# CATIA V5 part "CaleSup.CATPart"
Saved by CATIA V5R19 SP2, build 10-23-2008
Part number: CaleSup
Bounding box of the stored display mesh (mm): x 0 to 16, y 0 to 96, z 0 to 53.5
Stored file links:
  D:\SCHOOL\FRANCE\BANC_POUTRE_EN_MOUSSE\CaleSup.CATPart
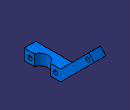
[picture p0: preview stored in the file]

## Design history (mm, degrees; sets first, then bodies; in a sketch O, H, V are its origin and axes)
AxisSystem1: origin (0, 0, 0), X (1, 0, 0), Y (0, 1, 0), Z (0, 0, 1)
Body1 (main body)
  Sketch1 on YZ plane of AxisSystem1, origin (0, 0, 0), H (0, 1, 0), V (0, 0, 1)
    point P1 (0, 15)
    line L1 (0, 15) -> (0, 0)
    line L2 (0, 0) -> (50, 0)
    point P2 (50, 0)
    line L3 (50, 0) -> (96, 46)
    point P3 (96, 46)
    line L4 (96, 46) -> (88.5, 53.5)
    line L5 (88.5, 53.5) -> (50, 15)
    line L6 (50, 15) -> (0, 15)
    construction line L7 (-32.6409, 0) -> (133.7668, 0)
    point P6 (-32.6409, 0)
    axis line L8 (0, 62.3177) -> (0, -36.8999)
    point P8 (0, 62.3177)
    angle L7 L3 = 45
    length L6 = 50
    distance P2 L8 = 50
    distance P3 L7 = 46
    distance L6 L2 = 15
    coincidence: P1 V, P6 H, L7 H, P8 V
    vertical: L1 V, L8 V
    horizontal: L2 H, L6 H
    perpendicularity: L4 L3
    parallelism: L3 L5
  Pad1: profile Sketch1, direction (1, 0, 0), length 20
  Sketch2 on end face of Pad1, origin (20, 85.234, 39.5673), H (0, 1, 0), V (0, 0, 1)
    point P1 (2.266, 5.4327)
    axis line L1 (-24.0475, -20.8808) -> (18.1423, 21.309)
    reference projected line E1 (-2.734, 7.9327) -> (-35.663, -24.9963) from edge [face of Pad1 from Sketch1.L5 | end face of Pad1]
    reference projected line E2 (-35.234, -39.5673) -> (4.766, 0.4327) from edge [face of Pad1 from Sketch1.L3 | end face of Pad1]
    reference projected line E3 (-85.234, -39.5673) -> (-35.234, -39.5673) from edge [face of Pad1 from Sketch1.L2 | end face of Pad1]
    distance P1 E3 = 45
    symmetry: E1 E2 L1
    coincidence: P1 L1
  Hole1: placed by Sketch2, at (20, 87.5, 45) direction (-1, 0, 0), diameter 6, through (limit type 6)
  Sketch3 on start face of Pad1, origin (0, 4.4213, 7.6038), H (0, 1, 0), V (0, 0, -1)
    point P1 (3.5787, 0.1038)
    axis line L1 (-24.2287, 0.1038) -> (70.7488, 0.1038)
    reference projected line E1 (-4.4213, 7.6038) -> (45.5787, 7.6038) from edge [start face of Pad1 | face of Pad1 from Sketch1.L2]
    reference projected line E2 (45.5787, -7.3962) -> (-4.4213, -7.3962) from edge [start face of Pad1 | face of Pad1 from Sketch1.L6]
    reference projected line E3 (-4.4213, -7.3962) -> (-4.4213, 7.6038) from edge [start face of Pad1 | face of Pad1 from Sketch1.L1]
    distance E3 P1 = 8
    horizontal: L1 H
    symmetry: E1 E2 L1
    coincidence: P1 L1
  Hole2: placed by Sketch3, at (0, 8, 7.5) direction (1, 0, 0), diameter 6, through (limit type 6), counterbore diameter 10, counterbore depth 5
  RectPattern1: of Hole2, direction 1 instances 2, spacing 35, along edge [start face of Pad1 | face of Pad1 from Sketch1.L2]
  Sketch4 on face of Pad1 from Sketch1.L2, origin (0, 0, 0), H (1, 0, 0), V (0, -1, 0)
    arc A1 centre (20, -25) radius 12 from (20, -13) to (20, -37) ccw
    point P1 (20, -25)
    point P2 (20, -13)
    point P3 (20, -37)
    reference projected line E1 (20, 0) -> (20, -50) from edge [face of Pad1 from Sketch1.L2 | end face of Pad1]
    reference projected line E2 (20, 0) -> (20, -50) from edge [face of Pad1 from Sketch1.L2 | end face of Pad1]
    reference projected line E3 (20, 0) -> (20, -50) from edge [face of Pad1 from Sketch1.L2 | end face of Pad1]
    reference projected line E4 (0, 0) -> (20, 0) from edge [face of Pad1 from Sketch1.L2 | face of Pad1 from Sketch1.L1]
    projected line E5 (20, 0) -> (20, -50) from edge [face of Pad1 from Sketch1.L2 | end face of Pad1]
    projected line E6 (20, -13) -> (20, -37) from edge [face of Pad1 from Sketch1.L2 | end face of Pad1]
    distance E4 P1 = 25
    radius A1 = 12
    coincidence: P1 E1, P2 E2, P3 E3
  Pocket1: profile Sketch4, direction (0, 0, 1), through (limit type 6)
  Sketch5 on face of Pad1 from Sketch1.L2, origin (0, 0, 0), H (1, 0, 0), V (0, -1, 0)
    line L1 (16, 0) -> (16, -96)
    projected line E1 (20, -37) -> (20, -50) from edge [face of Pad1 from Sketch1.L2 | end face of Pad1]
    projected line E2 (20, -50) -> (20, -96) from edge [face of Pad1 from Sketch1.L3 | end face of Pad1]
    point P4 (20, -96)
    projected line E3 (20, 0) -> (20, -13) from edge [face of Pad1 from Sketch1.L2 | end face of Pad1]
    point P5 (20, 0)
    projected line E4 (0, 0) -> (20, 0) from edge [face of Pad1 from Sketch1.L2 | face of Pad1 from Sketch1.L1]
    projected line E5 (16, 0) -> (20, 0) from edge [face of Pad1 from Sketch1.L2 | face of Pad1 from Sketch1.L1]
    point P8 (20, 0)
    projected line E6 (0, -96) -> (20, -96) from edge [face of Pad1 from Sketch1.L4 | face of Pad1 from Sketch1.L3]
    projected line E7 (16, -96) -> (20, -96) from edge [face of Pad1 from Sketch1.L4 | face of Pad1 from Sketch1.L3]
    point P10 (20, -96)
    line L2 (20, -13) -> (20, -37)
    point P11 (16, 0)
    point P12 (16, -96)
    point P13 (16, -96)
    distance L1 E2 = 4
    vertical: L1 V, L2 V
    coincidence: E4 P11, L1 P12, E6 P13, P4 P10, P5 P8, P12 P13
  Pocket2: profile Sketch5, direction (0, 0, 1), through (limit type 6)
